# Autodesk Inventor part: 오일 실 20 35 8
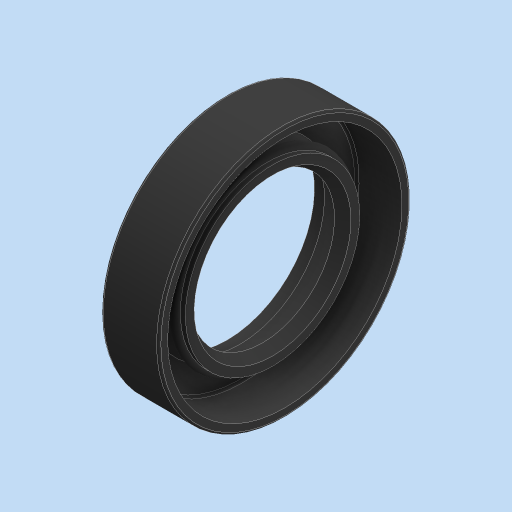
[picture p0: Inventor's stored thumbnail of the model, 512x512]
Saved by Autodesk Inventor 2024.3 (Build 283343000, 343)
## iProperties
Created: 2026-01
Part Number: 오일 실 20 35 8
Material: 고무
Description: 오일-실
Document SubType Name: Modeling
Designer: PC2-02
Density: 0.93 g/cm^3
Appearance: 기본값
Author: jhkim
Sending System: Autodesk Inventor 2026
Preprocessor: ST-DEVELOPER v20.1
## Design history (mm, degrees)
node "오일 실 20 35 81"
node "솔리드1"
body "Solid1"
